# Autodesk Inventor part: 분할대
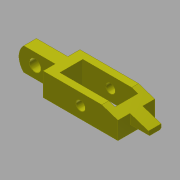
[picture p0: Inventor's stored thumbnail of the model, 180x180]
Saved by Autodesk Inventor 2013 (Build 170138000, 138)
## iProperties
Created: 2016-11
Part Number: 분할대
Material: 강철, 연강
Document SubType Name: Modeling
Designer: mduedu
Density: 1 g/cm^3
Author: mduedu
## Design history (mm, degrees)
sketch "스케치1"
  geometry: L1 (32.5, 16)-(-32.5, 16); L2 (-32.5, 16)-(-32.5, -16); L3 (-32.5, -16)-(32.5, -16); L4 (32.5, -16)-(32.5, 16); L5 (24, 10)-(-24, 10); L6 (-24, 10)-(-24, -10); L7 (-24, -10)-(24, -10); L8 (24, -10)-(24, 10); L9 (24, 0)-(-24, 0); L10 (0, -16)-(0, 16); 4 further points
  constraints: 20 end point, 7 midpoint, 4 parallel, 2 coincident, 2 horizontal, 2 perpendicular, 1 horizontal alignment
  dimensions: "d0" = 20 distance of L5.end L6.end; "d2" = 32 distance between parallel lines of L1 L3; "d3" = 48 distance of L5.start L5.end; "d4" = 65 distance of L1.start L1.end
extrude "돌출1" new body sketch "스케치1" distance "d5" = 20; taper "d6" = 0 deg
sketch "스케치2"
  geometry: L1 (0, 0)-(65, 0) reference; L2 (65, 0)-(65, 20) reference; L3 (0, 20)-(65, 20) reference; L4 (0, 0)-(0, 20) reference; L5 (32.5, 0)-(32.5, 20); C1 r 4 at (32.5, 10)
  constraints: 2 end point, 2 midpoint, 1 centre point
  dimensions: "d7" = 8 diameter of C1
extrude "돌출2" cut sketch "스케치2" stored distance "d8" = 20; taper "d9" = 0 deg
chamfer "모따기1" distance "d10" = 0.2; stored, may be unused: second distance "d11" = 2, angle "d12" = 45 deg
sketch "스케치3"
  geometry: L1 (-32.5, 0)-(-32.5, 20) reference; L2 (-32.5, 20)-(-59.798, 20); L3 (-64, 20)-(-64, 0); L4 (-64, 0)-(-59.798, 0); L5 (-32.5, 0)-(-32.5, 20); L6 (-59.798, 20)-(-64, 20); L7 (-59.798, 0)-(-32.5, 0); C1 r 4.2 at (0, 10) reference; C2 r 5 at (-50, 10); A1 r 14 centre (-50, 10) between (-59.798, 20) and (-59.798, 0); 1 further point
  constraints: 12 end point, 5 parallel, 2 centre point, 2 horizontal, 2 perpendicular, 2 point on circle, 1 coincident, 1 horizontal alignment, 1 tangent
  dimensions: "d13" = 64 distance from line of L3 C1.centre; "d14" = 14 radius of A1; "d15" = 10 diameter of C2
extrude "돌출3" join sketch "스케치3" stored distance "d16" = 11; taper "d17" = 0 deg
sketch "스케치4"
  geometry: L1 (32.5, 0)-(32.5, 20) reference; L2 (32.5, 20)-(48.5, 20); L3 (48.5, 20)-(48.5, 6); L4 (48.5, 6)-(32.5, 6); L5 (32.5, 6)-(32.5, 20); L6 (32.5, 0)-(-32.5, 0) reference; 1 further point
  constraints: 8 end point, 2 parallel, 1 horizontal, 1 perpendicular
  dimensions: "d18" = 16 distance of L1.end L2.end; "d19" = 6 distance between parallel lines of L4 L6
extrude "돌출4" join sketch "스케치4" stored distance "d20" = 11; taper "d21" = 0 deg
chamfer "모따기2" distance "d22" = 30; stored, may be unused: second distance "d23" = 10, angle "d24" = 45 deg
chamfer "모따기3" distance "d25" = 1; stored, may be unused: second distance "d26" = 10, angle "d27" = 45 deg
chamfer "모따기4" distance "d28" = 0.2; stored, may be unused: second distance "d29" = 10, angle "d30" = 45 deg
node "솔리드1"
node "투영된 루프1"
